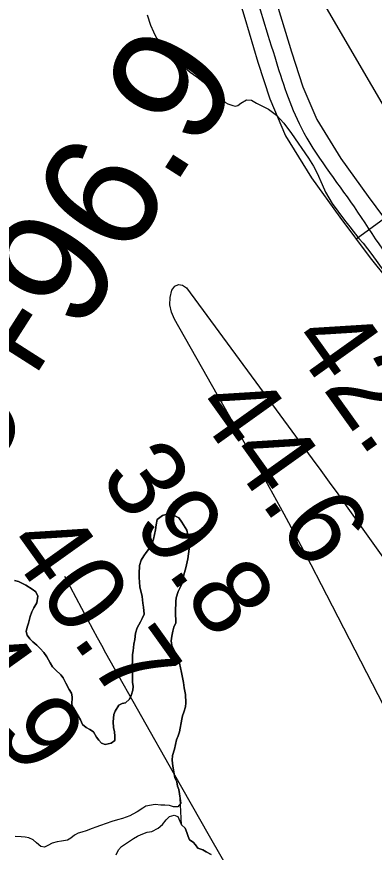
# Model space of a CAD drawing. Extents: x 3187622 to 3225504, y 800805 to 826213.
# Drawn here: x 3198035 to 3198341, y 817453 to 818168 of the extents above; entities that cross this region are included whole.
import ezdxf

# ---------------------------------------------------------------- set-up
doc = ezdxf.new("R2010")
doc.units = 0
for name, color, linetype in [('V-RIVR-RANG', 7, 'Continuous'), ('V-ROAD-CNTR', 7, 'Continuous'), ('V-SITE-VEGE', 7, 'Continuous'), ('V-SURV-IDEN', 7, 'Continuous'), ('V-TOPO-MINR', 7, 'Continuous'), ('V-TOPO-SHOR', 7, 'Continuous')]:
    doc.layers.add(name, color=color, linetype=linetype)

msp = doc.modelspace()

# ---------------------------------------------------------------- linework, layer by layer
at = {"layer": 'V-ROAD-CNTR'}
msp.add_line((3198349.62, 817995.47), (3198325.52, 817977.61), dxfattribs=at)
for points in [[(3198218.74, 818204.7), (3198230.05, 818167.09), (3198241.41, 818129.32), (3198251.63, 818097.83), (3198264.98, 818066.38), (3198287.19, 818030.16), (3198311.5, 817996.53), (3198337.34, 817961.64), (3198365.39, 817927.05)], [(3198258.77, 818175.73), (3198270.05, 818138.27), (3198279.75, 818108.34), (3198291.72, 818080.16), (3198312.17, 818046.81), (3198335.71, 818014.25), (3198361.06, 817980.02)]]:
    msp.add_lwpolyline(points, dxfattribs=at)
msp.add_spline([(3197108.01, 817982.2), (3197162.34, 817991.13), (3197229.38, 818001.88), (3197259.08, 817993.64), (3197361.14, 818001.17), (3197493.79, 818058.56), (3197592.21, 818133.8), (3197727.97, 818194.32), (3197773.22, 818262.2), (3197795.85, 818360.06), (3197841.1, 818435.29), (3197893.71, 818488.46), (3197938.96, 818518.44), (3197968.94, 818533.71), (3198014.19, 818525.8), (3198044.74, 818495.82), (3198127.32, 818420.58), (3198203.12, 818307.45), (3198233.1, 818209.03), (3198255.73, 818133.8), (3198278.35, 818073.27), (3198323.61, 818005.39), (3198376.21, 817937.52), (3198429.38, 817900.18), (3198459.36, 817854.93), (3198466.72, 817832.3), (3198489.34, 817756.51), (3198504.61, 817703.9), (3198542.51, 817628.67), (3198633.02, 817530.24), (3198783.48, 817371.86), (3198859.28, 817221.4), (3198934.51, 817108.26)], degree=3, dxfattribs=at)
at = {"layer": 'V-SITE-VEGE'}
for p, q in [((3198146.5, 818169.85), (3198149.41, 818160.98)), ((3198149.41, 818160.98), (3198151.89, 818155.35)), ((3198151.89, 818155.35), (3198154.36, 818150.52)), ((3198154.36, 818150.52), (3198162.94, 818141.3)), ((3198162.94, 818141.3), (3198173.16, 818129.68)), ((3198173.16, 818129.68), (3198183.35, 818120.88)), ((3198183.35, 818120.88), (3198189.04, 818116.89)), ((3198189.04, 818116.89), (3198196.78, 818110.9)), ((3198196.78, 818110.9), (3198203.31, 818104.9)), ((3198203.31, 818104.9), (3198213.51, 818094.89)), ((3198226.85, 818094.2), (3198231.68, 818097.08)), ((3198231.68, 818097.08), (3198235.73, 818096.71)), ((3198213.51, 818094.89), (3198215.54, 818093.69)), ((3198215.54, 818093.69), (3198220, 818092.12)), ((3198220, 818092.12), (3198222.03, 818091.73)), ((3198222.03, 818091.73), (3198224.04, 818092.16)), ((3198224.04, 818092.16), (3198226.85, 818094.2)), ((3198235.73, 818096.71), (3198240.2, 818094.33)), ((3198240.2, 818094.33), (3198250.35, 818089.17)), ((3198250.35, 818089.17), (3198257.27, 818083.98)), ((3198257.27, 818083.98), (3198263.4, 818077.17)), ((3198263.4, 818077.17), (3198269.95, 818068.34)), ((3198269.95, 818068.34), (3198284.71, 818047.05)), ((3198284.71, 818047.05), (3198288.81, 818040.22)), ((3198288.81, 818040.22), (3198292.1, 818034.18)), ((3198292.1, 818034.18), (3198296.24, 818024.52)), ((3198296.24, 818024.52), (3198299.13, 818018.08)), ((3198299.13, 818018.08), (3198304.88, 818008.43)), ((3198304.88, 818008.43), (3198315.52, 817993.98)), ((3198315.52, 817993.98), (3198320.03, 817988.36)), ((3198320.03, 817988.36), (3198327.8, 817978.33)), ((3198327.8, 817978.33), (3198331.48, 817974.32)), ((3198331.48, 817974.32), (3198338.85, 817964.69)), ((3198338.85, 817964.69), (3198349.09, 817950.23)), ((3198159.83, 817740.9), (3198155.25, 817737.56)), ((3198162.67, 817742.02), (3198159.83, 817740.9)), ((3198167.28, 817742.28), (3198162.67, 817742.02)), ((3198173.68, 817739.05), (3198167.28, 817742.28)), ((3198154.41, 817733.16), (3198153.79, 817728.76)), ((3198155.25, 817737.56), (3198154.41, 817733.16)), ((3198176.35, 817735.34), (3198173.68, 817739.05)), ((3198180.58, 817728.58), (3198176.35, 817735.34)), ((3198153.79, 817728.76), (3198152.73, 817724.8)), ((3198182.2, 817720.47), (3198180.58, 817728.58)), ((3198151.89, 817720.62), (3198150.4, 817715.77)), ((3198152.73, 817724.8), (3198151.89, 817720.62)), ((3198182.68, 817715.64), (3198182.2, 817720.47)), ((3198147.58, 817711.8), (3198145.63, 817709.36)), ((3198150.4, 817715.77), (3198147.58, 817711.8)), ((3198181.25, 817703.99), (3198182.49, 817712.35)), ((3198182.49, 817712.35), (3198182.68, 817715.64)), ((3198143.68, 817706.49), (3198141.52, 817702.73)), ((3198145.63, 817709.36), (3198143.68, 817706.49)), ((3198179.57, 817696.29), (3198181.25, 817703.99)), ((3198140.03, 817698.11), (3198139.65, 817691.08)), ((3198141.52, 817702.73), (3198140.03, 817698.11)), ((3198178.09, 817690.12), (3198179.57, 817696.29)), ((3198139.65, 817691.08), (3198139.68, 817688)), ((3198177.46, 817686.82), (3198178.09, 817690.12)), ((3198036.51, 817684.61), (3198033.2, 817685.46)), ((3198042.9, 817681.38), (3198036.51, 817684.61)), ((3198139.68, 817688), (3198140.2, 817679.88)), ((3198174.9, 817679.33), (3198176.19, 817682.42)), ((3198176.19, 817682.42), (3198177.46, 817686.82)), ((3198048.21, 817677.92), (3198042.9, 817681.38)), ((3198051.3, 817675.53), (3198048.21, 817677.92)), ((3198053.09, 817672.03), (3198051.3, 817675.53)), ((3198140.2, 817679.88), (3198142.25, 817671.78)), ((3198171.47, 817670.52), (3198173.18, 817675.8)), ((3198173.18, 817675.8), (3198174.9, 817679.33)), ((3198052.05, 817666.32), (3198053.09, 817672.03)), ((3198142.25, 817671.78), (3198142.75, 817666.07)), ((3198171.06, 817667.44), (3198171.47, 817670.52)), ((3198047.95, 817658.59), (3198049.68, 817661.9)), ((3198049.68, 817661.9), (3198052.05, 817666.32)), ((3198142.75, 817666.07), (3198143.44, 817662.57)), ((3198143.44, 817662.57), (3198143.93, 817656.64)), ((3198170.7, 817658.65), (3198171.06, 817667.44)), ((3198044.97, 817648.68), (3198046.45, 817654.4)), ((3198046.45, 817654.4), (3198047.95, 817658.59)), ((3198143.93, 817656.64), (3198142.43, 817652.68)), ((3198171.01, 817649.21), (3198170.7, 817658.65)), ((3198043.9, 817645.38), (3198044.97, 817648.68)), ((3198140.92, 817649.81), (3198138.11, 817644.95)), ((3198142.43, 817652.68), (3198140.92, 817649.81)), ((3198169.51, 817645.25), (3198171.01, 817649.21)), ((3198043.06, 817641.64), (3198043.9, 817645.38)), ((3198043.97, 817638.57), (3198043.06, 817641.64)), ((3198136.62, 817640.1), (3198136.01, 817634.83)), ((3198138.11, 817644.95), (3198136.62, 817640.1)), ((3198167.61, 817637.54), (3198168.44, 817641.94)), ((3198168.44, 817641.94), (3198169.51, 817645.25)), ((3198046.2, 817635.3), (3198043.97, 817638.57)), ((3198048.85, 817632.69), (3198046.2, 817635.3)), ((3198052.17, 817630.08), (3198048.85, 817632.69)), ((3198136.01, 817634.83), (3198135.17, 817630.87)), ((3198167.21, 817633.81), (3198167.61, 817637.54)), ((3198167.68, 817629.64), (3198167.21, 817633.81)), ((3198055.06, 817627.04), (3198052.17, 817630.08)), ((3198058.16, 817623.77), (3198055.06, 817627.04)), ((3198134.57, 817625.15), (3198134.16, 817622.08)), ((3198135.17, 817630.87), (3198134.57, 817625.15)), ((3198169.93, 817624.83), (3198167.68, 817629.64)), ((3198172.4, 817618.7), (3198169.93, 817624.83)), ((3198060.61, 817620.06), (3198058.16, 817623.77)), ((3198063.52, 817614.82), (3198060.61, 817620.06)), ((3198134.16, 817622.08), (3198133.99, 817616.36)), ((3198174.2, 817614.55), (3198172.4, 817618.7)), ((3198065.53, 817611.33), (3198063.52, 817614.82)), ((3198068.19, 817608.71), (3198065.53, 817611.33)), ((3198133.99, 817616.36), (3198133.81, 817612.63)), ((3198133.81, 817612.63), (3198133.91, 817601.87)), ((3198175.11, 817610.6), (3198174.2, 817614.55)), ((3198176.03, 817606.44), (3198175.11, 817610.6)), ((3198072.83, 817604.58), (3198068.19, 817608.71)), ((3198074.62, 817601.97), (3198072.83, 817604.58)), ((3198177.64, 817598.11), (3198176.03, 817606.44)), ((3198077.07, 817597.38), (3198074.62, 817601.97)), ((3198079.98, 817591.92), (3198077.07, 817597.38)), ((3198133.91, 817601.87), (3198133.95, 817598.14)), ((3198133.95, 817598.14), (3198134.64, 817594.63)), ((3198178.35, 817593.51), (3198177.64, 817598.11)), ((3198081.77, 817588.86), (3198079.98, 817591.92)), ((3198082.46, 817585.57), (3198081.77, 817588.86)), ((3198134.45, 817591.33), (3198132.95, 817586.93)), ((3198134.64, 817594.63), (3198134.45, 817591.33)), ((3198179.28, 817587.58), (3198178.35, 817593.51)), ((3198082.08, 817578.98), (3198082.46, 817585.57)), ((3198131.45, 817583.62), (3198128.18, 817580.52)), ((3198132.95, 817586.93), (3198131.45, 817583.62)), ((3198179.79, 817580.56), (3198179.28, 817587.58)), ((3198083.65, 817576.14), (3198082.08, 817578.98)), ((3198085.65, 817572.86), (3198083.65, 817576.14)), ((3198122.27, 817578.48), (3198119.25, 817573.4)), ((3198125.11, 817580.05), (3198122.27, 817578.48)), ((3198128.18, 817580.52), (3198125.11, 817580.05)), ((3198177.89, 817572.64), (3198179.38, 817577.26)), ((3198179.38, 817577.26), (3198179.79, 817580.56)), ((3198089.45, 817566.09), (3198085.65, 817572.86)), ((3198117.96, 817570.54), (3198117.36, 817564.16)), ((3198119.25, 817573.4), (3198117.96, 817570.54)), ((3198176.19, 817566.48), (3198176.82, 817569.56)), ((3198176.82, 817569.56), (3198177.89, 817572.64)), ((3198091.25, 817561.94), (3198089.45, 817566.09)), ((3198094.35, 817559.33), (3198091.25, 817561.94)), ((3198117.36, 817564.16), (3198117.84, 817559.33)), ((3198174.31, 817555.7), (3198176.19, 817566.48)), ((3198097.65, 817557.83), (3198094.35, 817559.33)), ((3198100.75, 817555.66), (3198097.65, 817557.83)), ((3198103.21, 817551.29), (3198100.75, 817555.66)), ((3198117.84, 817559.33), (3198118.53, 817555.83)), ((3198118.53, 817555.83), (3198119.01, 817552.1)), ((3198173.02, 817552.39), (3198174.31, 817555.7)), ((3198105.21, 817548.46), (3198103.21, 817551.29)), ((3198107.43, 817546.06), (3198105.21, 817548.46)), ((3198110.73, 817544.78), (3198107.43, 817546.06)), ((3198115.77, 817546.14), (3198110.73, 817544.78)), ((3198119.04, 817548.37), (3198115.77, 817546.14)), ((3198119.01, 817552.1), (3198119.04, 817548.37)), ((3198169.84, 817540.94), (3198171.74, 817548.86)), ((3198171.74, 817548.86), (3198173.02, 817552.39)), ((3198168.36, 817535.44), (3198169.84, 817540.94)), ((3198167.95, 817531.48), (3198168.36, 817535.44)), ((3198168.66, 817526.44), (3198167.95, 817531.48)), ((3198169.37, 817521.39), (3198168.66, 817526.44)), ((3198170.29, 817516.35), (3198169.37, 817521.39)), ((3198171.86, 817512.85), (3198170.29, 817516.35)), ((3198172.56, 817509.12), (3198171.86, 817512.85)), ((3198173.68, 817506.28), (3198172.56, 817509.12)), ((3198174.38, 817502.56), (3198173.68, 817506.28)), ((3198174.83, 817498.81), (3198174.38, 817502.56)), ((3198175.87, 817475.97), (3198174.83, 817498.81)), ((3198179.06, 817473.15), (3198175.87, 817475.97)), ((3198180.46, 817469.55), (3198179.06, 817473.15)), ((3198181.53, 817466.11), (3198180.46, 817469.55)), ((3198182.94, 817463.32), (3198181.53, 817466.11)), ((3198185.83, 817461.32), (3198182.94, 817463.32)), ((3198188.06, 817459), (3198185.83, 817461.32)), ((3198189.79, 817456.2), (3198188.06, 817459)), ((3198194.31, 817454.65), (3198189.79, 817456.2)), ((3198197.2, 817452.97), (3198194.31, 817454.65)), ((3198201.39, 817450.78), (3198197.2, 817452.97))]:
    msp.add_line(p, q, dxfattribs=at)
at = {"layer": 'V-TOPO-MINR'}
for points in [[(3198020.05, 818661.79), (3198038.46, 818628.67), (3198052.11, 818604.36), (3198077.6, 818559.22), (3198103.24, 818514.16), (3198129.1, 818469.23), (3198155.09, 818424.38), (3198431.36, 817950.37), (3198449.56, 817919.41), (3198467.9, 817888.54), (3198486.48, 817857.8), (3198505.2, 817827.15), (3198515.79, 817809.96), (3198540.1, 817770.89), (3198564.63, 817731.98), (3198589.51, 817693.28), (3198614.63, 817654.73), (3198782.4, 817399.66)], [(3198363.63, 817549.84), (3198300.38, 817672.88), (3198282.27, 817707.57), (3198263.87, 817742.11), (3198245.04, 817776.41), (3198225.91, 817810.55), (3198169.9, 817909.12), (3198167.43, 817915.21), (3198166.04, 817921.4), (3198166.26, 817927.75), (3198167.57, 817934.19), (3198170.33, 817937.36), (3198173.33, 817938.99), (3198176.67, 817938.32), (3198180.25, 817936.12), (3198287.71, 817789.71), (3198295.04, 817779.67), (3198302.34, 817769.62), (3198309.59, 817759.53), (3198316.81, 817749.42), (3198385.74, 817652.46)], [(3198791.38, 816276.06), (3198652.63, 816645.84), (3198642.18, 816672.82), (3198631.35, 816699.64), (3198619.95, 816726.22), (3198608.18, 816752.65), (3198595.74, 816778.76), (3198582.8, 816804.61), (3198569.1, 816830.07), (3198554.91, 816855.27), (3198293.59, 817303.67), (3198262.2, 817357.78), (3198230.97, 817411.98), (3198199.95, 817466.31), (3198169.08, 817520.72), (3198114.98, 817616.54), (3198111.3, 817623.12), (3198107.65, 817629.71), (3198104.06, 817636.33), (3198100.5, 817642.97), (3198076.11, 817688.84)]]:
    msp.add_lwpolyline(points, dxfattribs=at)
at = {"layer": 'V-TOPO-SHOR'}
for points in [[(3198110.73, 817544.78), (3198115.77, 817546.14), (3198119.04, 817548.37), (3198119.01, 817552.1), (3198118.53, 817555.83), (3198117.84, 817559.33), (3198117.36, 817564.16), (3198117.96, 817570.54), (3198119.25, 817573.4), (3198122.27, 817578.48), (3198125.11, 817580.05), (3198128.18, 817580.52), (3198131.45, 817583.62), (3198132.95, 817586.93), (3198134.45, 817591.33), (3198134.64, 817594.63), (3198133.94, 817598.14), (3198133.91, 817601.87), (3198133.81, 817612.63), (3198133.99, 817616.36), (3198134.16, 817622.08), (3198134.57, 817625.15), (3198135.17, 817630.87), (3198136.01, 817634.83), (3198136.62, 817640.1), (3198138.11, 817644.95), (3198140.92, 817649.81), (3198142.43, 817652.68), (3198143.93, 817656.64), (3198143.44, 817662.57), (3198142.75, 817666.07), (3198142.25, 817671.78), (3198140.2, 817679.88), (3198139.68, 817688), (3198139.65, 817691.08), (3198140.03, 817698.11), (3198141.52, 817702.73), (3198143.68, 817706.49), (3198145.63, 817709.36), (3198147.58, 817711.8), (3198150.4, 817715.78), (3198151.89, 817720.62), (3198152.73, 817724.8), (3198153.79, 817728.76), (3198154.41, 817733.16), (3198155.25, 817737.56), (3198159.83, 817740.9), (3198162.67, 817742.02), (3198167.28, 817742.28), (3198173.68, 817739.05), (3198176.35, 817735.34), (3198180.58, 817728.58), (3198182.2, 817720.47), (3198182.68, 817715.64), (3198182.49, 817712.34), (3198181.25, 817703.99), (3198179.57, 817696.29), (3198178.09, 817690.12), (3198177.46, 817686.82), (3198176.19, 817682.42), (3198174.9, 817679.33), (3198173.18, 817675.8), (3198171.47, 817670.52), (3198171.06, 817667.44), (3198170.7, 817658.65), (3198171.01, 817649.21), (3198169.51, 817645.25), (3198168.45, 817641.94), (3198167.61, 817637.54), (3198167.21, 817633.81), (3198167.68, 817629.64), (3198169.93, 817624.83), (3198172.4, 817618.7), (3198174.2, 817614.55), (3198175.11, 817610.6), (3198176.03, 817606.44), (3198177.64, 817598.11), (3198178.35, 817593.51), (3198179.28, 817587.58), (3198179.79, 817580.56), (3198179.38, 817577.26), (3198177.89, 817572.64), (3198176.82, 817569.56), (3198176.19, 817566.48), (3198174.31, 817555.7), (3198173.02, 817552.39), (3198171.74, 817548.86), (3198169.84, 817540.94), (3198168.36, 817535.44), (3198167.95, 817531.48), (3198168.66, 817526.44), (3198169.37, 817521.39), (3198170.29, 817516.35), (3198171.86, 817512.85), (3198172.56, 817509.12), (3198173.68, 817506.28), (3198174.38, 817502.56), (3198175.33, 817494.66), (3198172.94, 817491.56), (3198169.21, 817491.53), (3198165.69, 817492.59)], [(3198033.2, 817685.46), (3198036.51, 817684.61), (3198042.9, 817681.38), (3198048.21, 817677.92), (3198051.3, 817675.53), (3198053.09, 817672.03), (3198052.05, 817666.32), (3198049.68, 817661.9), (3198047.95, 817658.59), (3198046.45, 817654.4), (3198044.97, 817648.68), (3198043.9, 817645.38), (3198043.06, 817641.64), (3198043.97, 817638.57), (3198046.2, 817635.3), (3198048.85, 817632.69), (3198052.17, 817630.08), (3198055.06, 817627.04), (3198058.16, 817623.77), (3198060.61, 817620.06), (3198063.52, 817614.82), (3198065.53, 817611.33), (3198068.19, 817608.71), (3198072.83, 817604.58), (3198074.62, 817601.97), (3198077.08, 817597.38), (3198079.98, 817591.92), (3198081.77, 817588.86), (3198082.46, 817585.57), (3198082.08, 817578.98), (3198083.65, 817576.14), (3198085.65, 817572.86), (3198089.45, 817566.09), (3198091.25, 817561.94), (3198094.35, 817559.33), (3198097.65, 817557.83), (3198100.75, 817555.66), (3198103.21, 817551.29), (3198105.21, 817548.46), (3198107.43, 817546.06), (3198110.73, 817544.78)], [(3198145.49, 817492.18), (3198142.87, 817490.4), (3198138.07, 817487.28), (3198134.35, 817485.27), (3198131.73, 817483.71), (3198125.39, 817481.45), (3198121.22, 817480.31), (3198116.41, 817478.95), (3198111.59, 817477.15), (3198106.77, 817475.57), (3198102.62, 817473.99), (3198099.55, 817472.86), (3198094.52, 817470.84), (3198090.58, 817469.92), (3198087.52, 817468.79), (3198084.46, 817467.23), (3198081.19, 817464.78), (3198078.35, 817463), (3198073.3, 817462.07), (3198069.58, 817461.38), (3198065.2, 817460.24), (3198061.48, 817458.23), (3198058.64, 817456.89), (3198055.56, 817457.51), (3198052.02, 817460.77), (3198049.14, 817463.16), (3198045.39, 817464.88), (3198042.09, 817465.51), (3198038.79, 817465.7), (3198033.52, 817466.09)], [(3198165.69, 817492.59), (3198161.73, 817492.99), (3198158.22, 817492.96), (3198153.38, 817493.57), (3198145.49, 817492.18)], [(3198120.12, 817450.4), (3198122.15, 817454.74), (3198124.48, 817457.46), (3198127.12, 817459.2), (3198134.85, 817464.25), (3198138.31, 817466.46), (3198141.42, 817467.86), (3198146.66, 817469.71), (3198150.57, 817470.29), (3198155.99, 817473.11), (3198159.79, 817476.28), (3198162.95, 817480.45), (3198165.77, 817483.32), (3198169.69, 817484.22), (3198172.92, 817483.18), (3198174.47, 817479.09), (3198175.87, 817475.97), (3198179.06, 817473.15), (3198180.46, 817469.55), (3198181.53, 817466.11), (3198182.94, 817463.32), (3198185.83, 817461.32), (3198188.06, 817459), (3198189.79, 817456.2), (3198194.31, 817454.65), (3198197.2, 817452.97), (3198201.39, 817450.78)]]:
    msp.add_lwpolyline(points, dxfattribs=at)

# ---------------------------------------------------------------- texts
at = {"layer": 'V-RIVR-RANG'}
for s, p in [('42.3', (3198267.16, 817890.61)), ('44.6', (3198184.87, 817833.76)), ('39.8', (3198104.74, 817773.9)), ('40.7', (3198023.53, 817715.55)), ('34.9', (3197942.16, 817657.41))]:
    msp.add_text(s, height=67, rotation=305.55833, dxfattribs=at).set_placement(p)
at = {"layer": 'V-SURV-IDEN'}
for s, rotation, p in [('1416+96.9', 57.45166, (3197886.42, 817578.83)), ('1418+38.1', 17.12028, (3198047.27, 817257.51))]:
    msp.add_text(s, height=100, rotation=rotation, dxfattribs=at).set_placement(p)

doc.saveas('drawing.dxf')
